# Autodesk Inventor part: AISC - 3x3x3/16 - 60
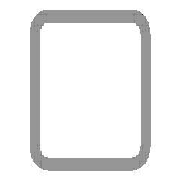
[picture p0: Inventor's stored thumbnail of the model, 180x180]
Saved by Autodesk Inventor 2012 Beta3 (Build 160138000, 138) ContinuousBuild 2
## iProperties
Created: 2011-01
Part Number: AISC - 3x3x3/16 - 60
Material: Steel, Mild
Description: Tube
Document SubType Name: Modeling
Standard: ANSI
Designer: Beta-8540w
Standards Organization: ANSI
Language: en-US
Size Designation: 3x3x3/16
Categories: <MemberInstance><Categories><Category DisplayName="Structural Shapes" InternalName="089c4875-fa83-4c05-b084-43b9cc11f5ed" Mnemonic="GRDR"><CategoryParameter Dis
Stock Number: 3x3x3/16
Density: 7.86 g/cm^3
IsCustomPart: 1
_CCFamilyMember: 9
_CCFamilyDisplayName: ANSI AISC (Square) - Tube
_FrameMemberDoc: Frame Member File
_Version: 15.0.0
_GetPNFromCC: 1
G_L: 60.000 in
G_W: 3.000 in
G_H: 3.000 in
Author: Beta-8540w
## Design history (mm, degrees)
node "Start plane"
node "End plane"
sketch "Sketch"
  geometry: L1 (-38.1, -28.575)-(-38.1, 28.575); L2 (-28.575, 38.1)-(28.575, 38.1); L3 (38.1, 28.575)-(38.1, -28.575); L4 (28.575, -38.1)-(-28.575, -38.1); L5 (-28.575, 33.337)-(28.575, 33.338); L6 (33.338, 28.575)-(33.338, -28.575); L7 (28.575, -33.337)-(-28.575, -33.338); L8 (-33.338, -28.575)-(-33.338, 28.575); L9 (0, 56.102)-(0, -56.102) reference; L10 (-56.102, 0)-(56.102, 0) reference; A1 r 9.525 centre (-28.575, -28.575) between (-38.1, -28.575) and (-28.575, -38.1); A2 r 9.525 centre (-28.575, 28.575) between (-28.575, 38.1) and (-38.1, 28.575); A3 r 9.525 centre (28.575, 28.575) between (38.1, 28.575) and (28.575, 38.1); A4 r 9.525 centre (28.575, -28.575) between (28.575, -38.1) and (38.1, -28.575); A5 r 4.763 centre (-28.575, 28.575) between (-28.575, 33.337) and (-33.338, 28.575); A6 r 4.763 centre (28.575, 28.575) between (33.338, 28.575) and (28.575, 33.338); A7 r 4.763 centre (28.575, -28.575) between (28.575, -33.337) and (33.338, -28.575); A8 r 4.763 centre (-28.575, -28.575) between (-33.338, -28.575) and (-28.575, -33.338)
  constraints: 16 end point, 16 point on circle, 8 centre point, 8 tangent, 4 parallel, 3 equal radius, 2 perpendicular, 7 other
  dimensions: "d10" = 76.2 distance between parallel lines of L2 L4 (= G_H); "d11" = 76.2 distance between parallel lines of L1 L3 (= G_W); "d12" = 4.7625 distance between parallel lines of L3 L6 (= G_T); "d15" = 38.1 distance between parallel lines of L2 L10 (= 0.5 x d10); "d16" = 38.1 distance between parallel lines of L9 L3 (= 0.5 x d11); "d17" = 9.525 radius of A1 (= G_IR)
extrude "Body" new body sketch "Sketch" stored distance "d3" = 1524 (= G_L); taper "d4" = 0 deg
node "Driven Length"
  sketch "Sketch3"
    geometry: L1 (0, 0)-(10, 0) reference
    constraints: 2 end point, 1 horizontal
  workplane "Work Plane3"
  sketch "Sketch4"
    geometry: L1 (-2, 0)-(12, 0) reference; L2 (-2, 1524)-(12, 1524) reference
    dimensions: "d19" = 1524 distance between parallel lines of L1 L2 (derived)
body "Solid1"
other parameters: "G_W" = 76.2 [user parameter; used in 1 equation term], "G_H" = 76.2 [user parameter; used in 1 equation term], "G_T" = 4.7625 [user parameter; used in 1 equation term], "G_IR" = 9.525 [user parameter; used in 1 equation term], "G_L" = 1524 (= d19) [user parameter; used in 1 equation term], "G_OFFSET_START" = 0 [user parameter; used in 1 equation term], "G_OFFSET_END" = 0 [user parameter; used in 1 equation term], "d13" = 0 (computed from G_OFFSET_START), "d14" = 1524 (= G_OFFSET_END + B_L), "B_L" = 1524 [user parameter; used in 1 equation term], "d18" = 90 deg
